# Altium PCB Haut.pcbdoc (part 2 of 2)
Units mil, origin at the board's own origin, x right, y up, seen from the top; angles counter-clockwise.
Board outline 4330.8 x 4330.8 mil, 2 copper layers (Top Layer, Bottom Layer), stack 62.2 mil thick; 77 components, 45 nets, 290 pads, 215 vias.
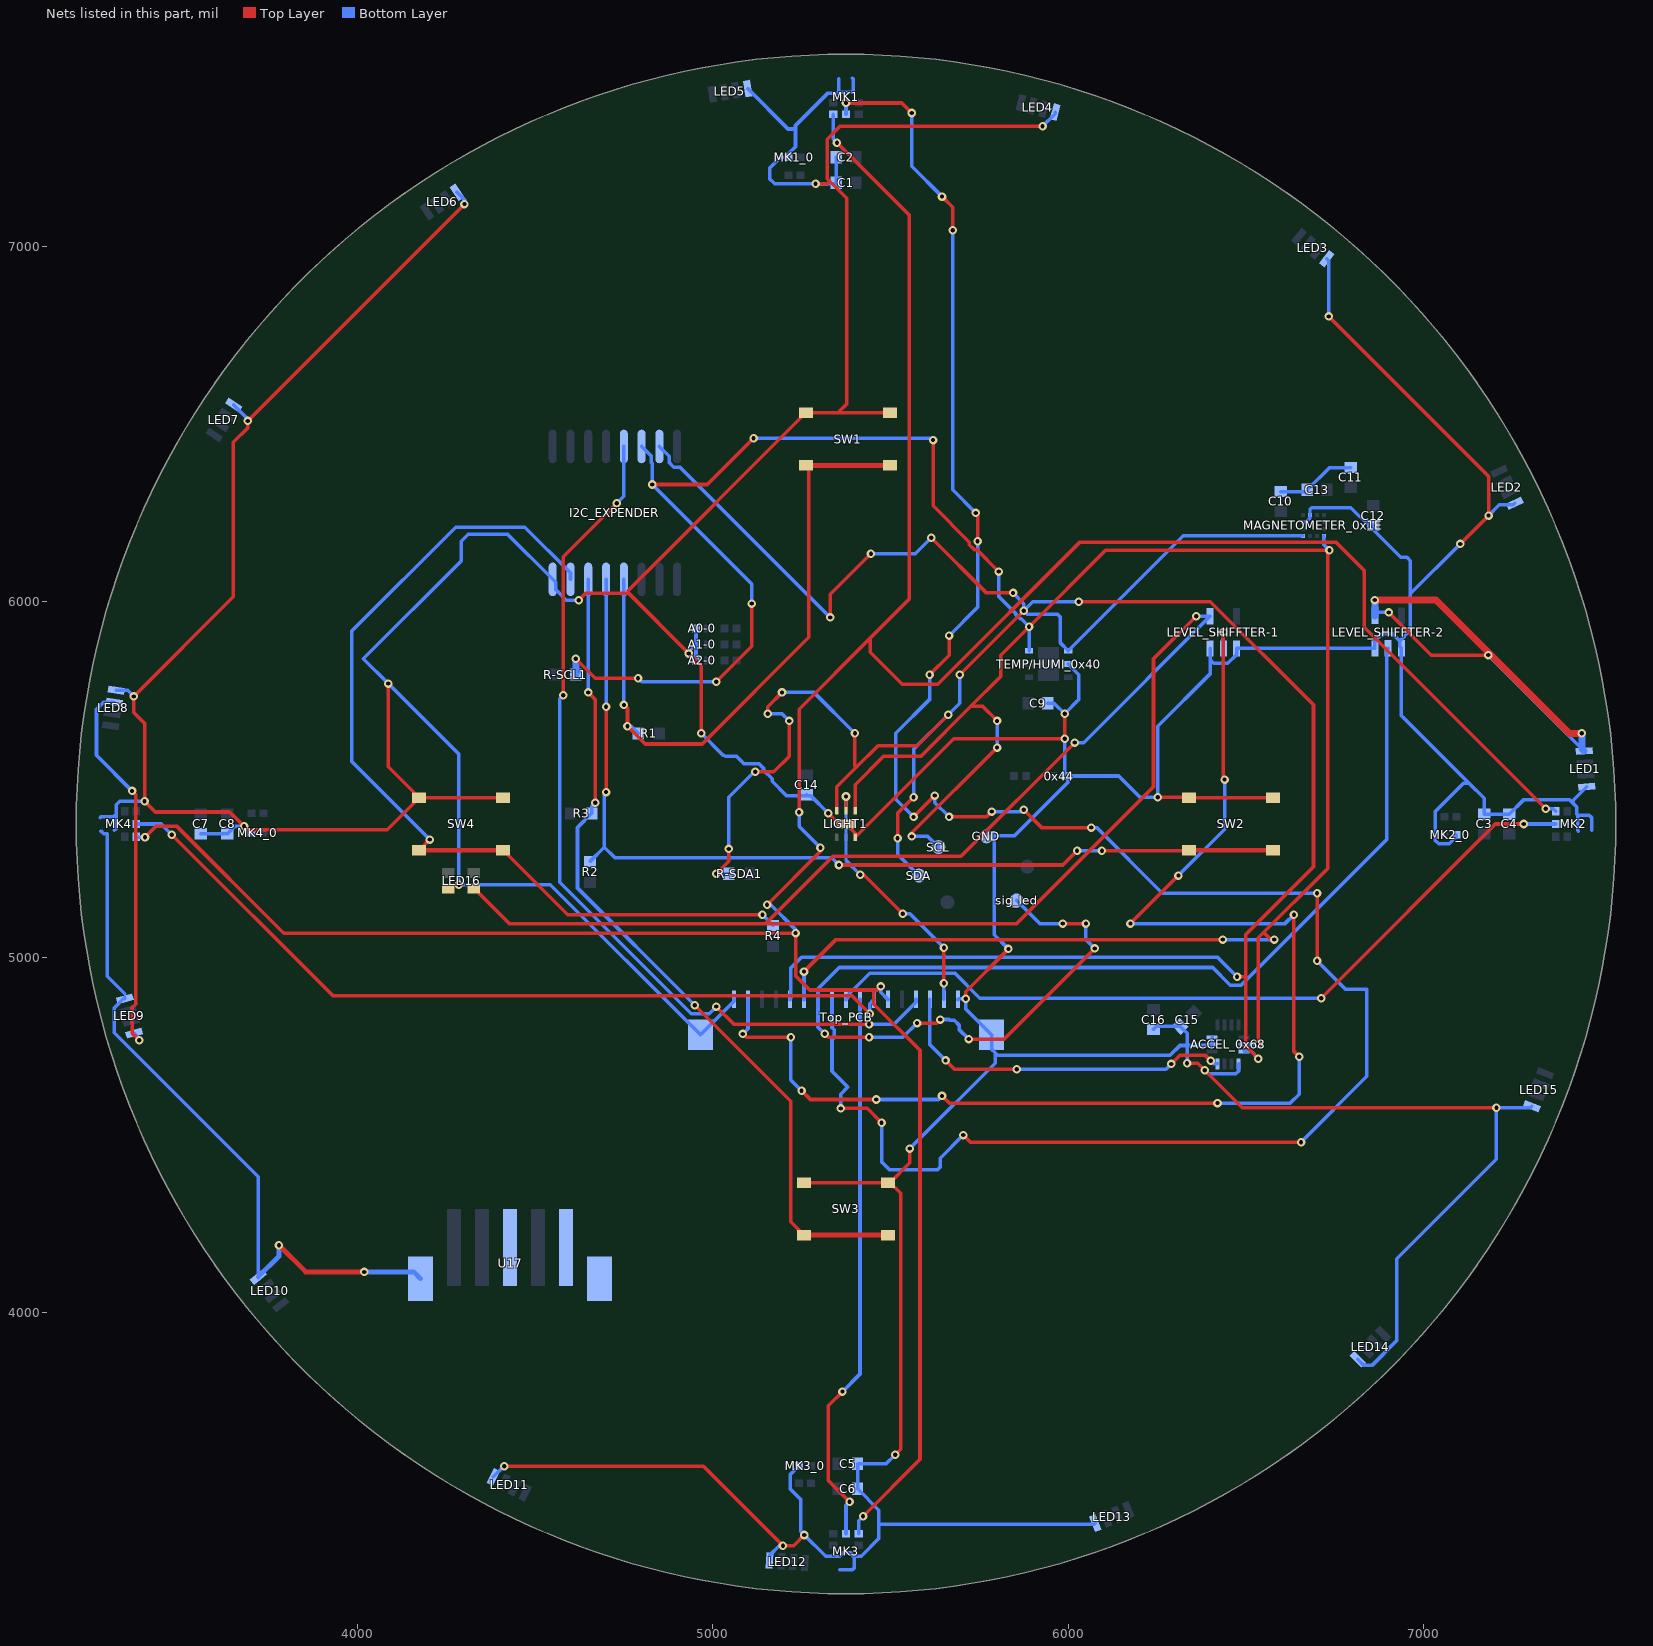
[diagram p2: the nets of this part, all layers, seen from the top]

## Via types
v1: diameter 24, hole 12, Top Layer to Bottom Layer, 215 vias

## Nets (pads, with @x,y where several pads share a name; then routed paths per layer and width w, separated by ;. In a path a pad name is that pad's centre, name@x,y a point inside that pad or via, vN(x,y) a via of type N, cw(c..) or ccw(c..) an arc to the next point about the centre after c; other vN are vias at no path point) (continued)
GND: 0x44.1 A0-0.1 A1-0.2 A2-0.2 ACCEL_0x68.1 ACCEL_0x68.6 ACCEL_0x68.7 C1.2 C2.2 C3.2 C4.2 C5.2 C6.2 C7.2 C8.2 C9.2 C10.1 C11.1 C12.1 C13.1 C14.1 C15.1 C16.1 GND.1 I2C_EXPENDER.8 LED1.4 LED2.4 LED3.4 LED4.4 LED5.4 LED6.4 LED7.4 LED8.4 LED9.4 LED10.4 LED11.4 LED12.4 LED13.4 LED14.4 LED15.4 LED16.2 LEVEL_SHIFFTER-1.1 LEVEL_SHIFFTER-1.3 LEVEL_SHIFFTER-2.1 LEVEL_SHIFFTER-2.3 LIGHT1.3 LIGHT1.7 MAGNETOMETER_0x1E.6 MAGNETOMETER_0x1E.8 MK1.3 MK1_0.2 MK2.3 MK2_0.2 MK3.3 MK3_0.2 MK4.3 MK4_0.2 SW1.1 SW1.2 SW2.1 SW2.2 SW3.1 SW3.2 SW4.1 SW4.2 TEMP/HUMI_0x40.2 Top_PCB.1 Top_PCB.17 Top_PCB.18 Top_PCB.19 U17.3 U17.5 U17.6 U17.7 | length 27844
  Top Layer w9.8: LIGHT1.7@5374.4,5374.4 5400,5348.8 LIGHT1.3@5400,5337 5677.4,5614.4 v1(5989.5,5614.4)
  Top Layer w10: v1(4086.8,5769.4) 4086.8,5535 SW4.1@4173.6,5448.2 ; LED16.2@4255.7,5193.4 4265.7,5203.4 v1(4285.7,5203.4) ; v1(4301.2,7118.2) v1(3691.2,6508.2) 3691.2,6488.2 3651.2,6448.2 3651.2,6013.2 v1(3371.2,5733.2) 3371.2,5688.2 3401.2,5658.2 v1(3401.2,5438.2) 3431.2,5408.2 3641.2,5408.2 v1(3681.2,5368.2) 3691.2,5358.2 4083.6,5358.2 SW4.1@4173.6,5448.2 ; SW4.2@4409.8,5448.2 SW4.1@4173.6,5448.2 ; v1(4413.4,3568) 4973.4,3568 v1(5197,3344.4) 5227,3344.4 v1(5257,3374.4) ; v1(4622.4,6004) 4642.4,6024 4762.4,6024 ; v1(4967,5629.4) 4967,5819.4 v1(4932.4,5854) 4762.4,6024 ; SW3.1@5256.3,4365.5 SW3.2@5492.5,4365.5 SW3.2@5498,4365.5 ; v1(5288.7,7175.3) 5322,7175.3 5328.8,7182.2 ; v1(5324.4,5404.4) 5354.4,5374.4 LIGHT1.7@5374.4,5374.4 ; SW1.2@5497.5,6530.9 5351.3,6530.9 ; v1(5513,3600.5) 5528,3615.5 5528,4335.5 SW3.2@5498,4365.5 ; v1(5553.9,4461.4) 5553.9,4421.4 SW3.2@5498,4365.5 ; v1(5711.4,4882.9) 5711.4,4902.9 v1(5831.4,5022.9) ; v1(5927.3,7336.9) 5357.3,7336.9 5321.3,7300.9 5321.3,7189.7 5328.8,7182.2 ; v1(5989.5,5614.4) v1(5989.5,5684.4) ; v1(6251.4,5449.4) 6337.8,5449.4 SW2.1@6339,5448.2 SW2.2@6575.2,5448.2 ; v1(6333.9,4701.4) 6363.9,4701.4 v1(6383.9,4681.4) 6488.9,4576.4 v1(7203.9,4576.4) ; v1(6732,6802.1) 7182,6352.1 v1(7182,6242.1) v1(7102,6162.1) ; 4762.4,6024 4762.4,6032 SW1.1@5261.3,6530.9 5351.3,6530.9 ; 5328.8,7182.2 5376.3,7134.7 5376.3,6555.9 5351.3,6530.9
  Top Layer w13.8: v1(3779.4,4189.4) 3854.4,4114.4 v1(4019.4,4114.4)
  Bottom Layer w9.8: C9.2@5942,5714.4 5959.5,5714.4 v1(5989.5,5684.4) ; C10.1@6597,6309.5 6667,6309.5 C13.1@6671.8,6314.4 6734.4,6377 C11.1@6794.4,6377 ; MAGNETOMETER_0x1E.6@6659.9,6224.2 6669.4,6224.2 6679.6,6234.4 MAGNETOMETER_0x1E.8@6679.6,6243.9 6679.6,6259.6 6684.4,6264.4 6794.4,6264.4 C12.1@6844.5,6214.3 ; C12.1@6857,6214.3 C12.1@6844.5,6214.3 ; 6962,6022.1 6962,6114.8 6952.4,6124.4 6934.4,6124.4 C12.1@6844.5,6214.3
  Bottom Layer w10: 3276.5,5392.2 3278.6,5394.3 3314.2,5394.3 3318.1,5398.2 3321.2,5398.2 ; 3278.6,5354.5 3286.5,5346.6 3296.3,5346.6 3296.3,4946.6 3345.9,4897 ; 3316.3,5356.6 3321.2,5361.5 3321.2,5398.2 ; LED8.4@3321.3,5750.4 3354,5750.4 v1(3371.2,5733.2) ; LED9.4@3345.9,4882.8 3345.9,4887 3315.9,4857 3315.9,4787 3721.2,4381.7 LED10.4@3721.2,4100.3 ; v1(3401.2,5438.2) 3331.2,5438.2 3321.2,5428.2 3321.2,5398.2 ; C7.2@3559.4,5346.8 C8.2@3634.4,5346.8 3655.8,5368.2 v1(3681.2,5368.2) 3683.5,5368.2 MK4_0.2@3702.4,5349.4 ; LED7.4@3651.8,6553 3691.2,6513.5 v1(3691.2,6508.2) ; LED6.4@4280.1,7151.7 4301.2,7130.6 v1(4301.2,7118.2) ; LED11.4@4382.4,3538 4412.4,3568 v1(4413.4,3568) ; v1(4622.4,6004) 4587.8,6004 4557.8,6034 4557.8,6054 I2C_EXPENDER.8@4549.4,6062.4 4422.4,6189.4 4311.8,6189.4 4291.8,6169.4 4291.8,6149.4 4291.8,6114.4 4016.8,5839.4 v1(4086.8,5769.4) 4285.7,5570.5 v1(4285.7,5203.4) 4542.9,5203.4 Top_PCB.19@4965,4781.4 5059.4,4875.9 Top_PCB.1@5059.4,4880.8 ; A0-0.1@4952.4,5924.4 A1-0.2@4952.4,5879.4 ; v1(4967,5629.4) 5027,5569.4 5036.8,5564.4 5066.8,5564.4 5086.8,5544.4 5128.9,5544.4 5142.4,5530.9 5142.4,5526.4 5166.8,5502 5166.8,5494.4 5206.8,5454.4 C14.1@5262,5454.4 ; LED5.4@5097.6,7443.2 5211.3,7329.4 5232.4,7329.4 ; LED12.4@5159.3,3302.9 5159.3,3316.8 5187,3344.4 v1(5197,3344.4) ; MK3_0.2@5242.4,3569.4 5217,3544 5217,3504.4 5247,3474.4 5247,3384.4 v1(5257,3374.4) 5317,3314.4 MK3.3@5357,3314.4 ; C14.1@5264.4,5456.8 C14.1@5262,5454.4 ; v1(5324.4,5404.4) 5274.4,5454.4 C14.1@5262,5454.4 ; C2.2@5346.8,7249.4 C1.2@5346.8,7178.1 5346.8,7175.3 v1(5288.7,7175.3) 5173.5,7175.3 5159.4,7189.4 5159.4,7219.4 5189.4,7249.4 MK1_0.2@5212.4,7249.4 5212.4,7259.4 5232.4,7279.4 5232.4,7329.4 ; 5354.5,3314.2 MK3.3@5357,3314.4 ; 5354.5,7470.2 5354.5,7434.6 5356.6,7432.5 ; 5356.6,3276.5 5392.2,3276.5 5394.3,3278.6 5397,3281.3 5397,3314.4 ; 5392.2,3316.3 5397,3314.4 ; 5392.2,7472.3 5394.3,7470.2 5394.3,7434.6 5392.2,7432.5 5356.6,7432.5 ; v1(5513,3600.5) 5486.9,3574.4 C5.2@5407,3574.4 C6.2@5407,3504.4 5467,3444.4 5467,3404.4 ; v1(5553.9,4461.4) 5793.9,4701.4 5793.9,4731.4 ; Top_PCB.17@5689.4,4880.8 5691.4,4882.9 v1(5711.4,4882.9) 5711.4,4853.8 Top_PCB.18@5783.9,4781.4 5783.9,4741.4 5793.9,4731.4 ; GND.1@5769.4,5349.4 5791.4,5349.4 ; v1(5831.4,5022.9) 5791.4,5062.9 5791.4,5349.4 ; v1(5927.3,7336.9) 5962.9,7372.5 LED4.4@5962.9,7376.9 ; v1(5989.5,5614.4) 5989.5,5511.3 0x44.1@5991.4,5509.4 ; v1(5989.5,5684.4) 6029.5,5724.4 6029.5,5794.4 TEMP/HUMI_0x40.2@5999.5,5824.4 ; LED13.4@6075.6,3407.6 6072.5,3404.4 5467,3404.4 ; C16.1@6239.4,4796.8 6247.5,4804.9 C15.1@6314.9,4804.9 6333.9,4786 6333.9,4751.4 ; v1(6333.9,4701.4) 6333.9,4751.4 ; v1(6383.9,4681.4) 6393.9,4671.4 6470.7,4671.4 6478.9,4679.6 ACCEL_0x68.1@6478.9,4699.6 ; LEVEL_SHIFFTER-1.3@6398.5,5868.2 6398.5,5836.4 ; ACCEL_0x68.7@6404.4,4774.1 ACCEL_0x68.6@6404.4,4754.4 6401.4,4751.4 6333.9,4751.4 ; LED3.4@6726.6,6964.4 6732,6959 v1(6732,6802.1) ; LED14.4@6813.9,3868.9 6831.4,3851.4 6853.9,3851.4 6923.9,3921.4 6923.9,4151.4 7203.9,4431.4 v1(7203.9,4576.4) 7299.9,4576.4 LED15.4@7303.6,4580.1 ; MK2_0.2@7091.4,5344.4 7091.4,5339 7071.4,5319 7041.4,5319 7031.4,5329 7031.4,5409 7111.4,5489 7126.8,5489 ; v1(7102,6162.1) 6962,6022.1 6962,5919 LEVEL_SHIFFTER-2.1@6932,5889 ; v1(7182,6242.1) 7212,6272.1 7251.1,6272.1 LED2.4@7255.6,6276.6 ; 7434.6,5354.5 7432.5,5356.6 7432.5,5392.2 7432.5,5399.4 ; LED1.4@7457.9,5479.3 7420,5441.4 7420,5432 ; 7472.3,5356.6 7472.3,5392.2 7470.2,5394.3 7465.1,5399.4 7432.5,5399.4 ; A1-0.2@4952.4,5879.4 A2-0.2@4952.4,5834.4 4932.8,5854 v1(4932.4,5854) 4932.4,5859.4 A1-0.2@4952.4,5879.4 ; 5232.4,7329.4 5232.4,7339.4 5322.4,7429.4 5353.5,7429.4 5356.6,7432.5 ; MK3.3@5357,3314.4 5367,3324.4 5387,3324.4 5397,3314.4 ; 5397,3314.4 5417,3314.4 5467,3364.4 5467,3404.4 ; 5791.4,5349.4 5798.9,5341.9 5848.9,5341.9 5998.9,5491.9 5998.9,5501.9 0x44.1@5991.4,5509.4 ; 5793.9,4731.4 5800.8,4724.4 6286.9,4724.4 6313.9,4751.4 6333.9,4751.4 ; 0x44.1@5991.4,5509.4 6141.4,5509.4 6201.4,5449.4 v1(6251.4,5449.4) 6251.4,5649.4 6398.5,5796.4 6398.5,5836.4 ; 6398.5,5836.4 6408.5,5826.4 6448.5,5826.4 6473.3,5851.2 LEVEL_SHIFFTER-1.1@6473.3,5868.2 6861.3,5868.2 LEVEL_SHIFFTER-2.3@6862,5869 6862,5889 6882,5909 6912,5909 LEVEL_SHIFFTER-2.1@6932,5889 ; LEVEL_SHIFFTER-2.1@6932,5889 6932,5873.8 LEVEL_SHIFFTER-2.1@6936.8,5869 6936.8,5679 7126.8,5489 ; 7126.8,5489 7169.4,5446.4 C3.2@7169.4,5402 C4.2@7240,5402 7280,5442 7410,5442 7420,5432 ; 7420,5432 7430,5422 7430,5402 7432.5,5399.4
  Bottom Layer w13.8: LED10.4@3721.2,4100.3 3779.4,4158.5 v1(3779.4,4189.4) ; v1(4019.4,4114.4) 4158.1,4114.4 U17.6@4177.4,4095.1
INT_ACCEL: ACCEL_0x68.4 Top_PCB.15 | length 993.8
  Top Layer w10: v1(5654.4,4709.4) 5679.4,4684.4 v1(5854.4,4684.4) ; v1(6289.4,4699.4) 6314.4,4724.4 6384.4,4724.4 v1(6400.5,4708.3)
  Bottom Layer w10: Top_PCB.15@5610.6,4880.8 5610.6,4753.2 v1(5654.4,4709.4) ; v1(5854.4,4684.4) 6274.4,4684.4 v1(6289.4,4699.4) ; v1@6399.4,4709.4 6409.2,4699.6 ACCEL_0x68.4@6419.9,4699.6
INT_EXT: I2C_EXPENDER.13 Top_PCB.14 | length 2518.1
  Top Layer w10: v1(4579.4,5736.4) 4579.4,6126.4 v1(4729.4,6276.4) ; v1(5009.4,4860.8) 5059.4,4810.8 v1(5439.4,4810.8)
  Bottom Layer w10: v1(4579.4,5736.4) 4569.4,5726.4 4569.4,5210.8 4939.4,4840.8 4989.4,4840.8 v1(5009.4,4860.8) ; v1(4729.4,6276.4) 4749.4,6296.4 I2C_EXPENDER.13@4749.4,6436.4 ; v1(5439.4,4810.8) 5509.4,4810.8 5571.3,4872.7 Top_PCB.14@5571.3,4880.8
INT_LUM: LIGHT1.5 Top_PCB.16 | length 742.7
  Top Layer w9.8: LIGHT1.5@5374.4,5411.8 v1(5374.4,5451.8) ; v1(5414.4,5231.8) 5424.4,5231.8 v1(5534.4,5121.8) ; v1(5650,4926.2) v1(5650,5026.2)
  Bottom Layer w9.8: v1(5374.4,5451.8) 5374.4,5271.8 v1(5414.4,5231.8) ; v1(5534.4,5121.8) 5554.4,5121.8 v1(5650,5026.2) ; Top_PCB.16@5650,4880.8 v1(5650,4926.2)
LED2: LED16.3 LEVEL_SHIFFTER-1.4 | length 5011.3
  Top Layer w10: LED16.3@4327.8,5193.4 4426.8,5094.4 ; v1(6017.8,5603.4) 5697.8,5283.4 5337.8,5283.4 5148.7,5094.4 ; v1(6359.4,5959.1) 6239.4,5839.1 6239.4,5479.4 5854.4,5094.4 5148.7,5094.4 ; 4426.8,5094.4 5148.7,5094.4 ; 4426.8,5094.4 4427.8,5093.4 5147.8,5093.4 5148.7,5094.4
  Bottom Layer w10: v1(6017.8,5603.4) 6042.8,5603.4 LEVEL_SHIFFTER-1.4@6398.5,5959.1 v1(6359.4,5959.1)
LED2-IN: LEVEL_SHIFFTER-1.2 Top_PCB.2 | length 3796.9
  Top Layer w10: v1(5084,4784) 5093.6,4774.4 v1(5219.4,4774.4) ; v1(5249.4,4624.4) 5274.4,4599.4 v1(5459.4,4599.4) ; v1(5644.4,4609.4) 5664.4,4589.4 v1(6419.4,4589.4) ; v1(6174.4,5094.4) v1(6309.4,5229.4) ; v1(6435.9,5914.4) 6435.9,5502.9 v1(6439.4,5499.4) ; v1(6634.4,5119.4) 6634.4,4734.4 v1(6649.4,4719.4)
  Bottom Layer w10: v1(5084,4784) 5098.8,4798.8 Top_PCB.2@5098.8,4880.8 ; v1(5219.4,4774.4) 5219.4,4654.4 v1(5249.4,4624.4) ; v1(5459.4,4599.4) 5634.4,4599.4 v1(5644.4,4609.4) ; v1(6174.4,5094.4) 6609.4,5094.4 v1(6634.4,5119.4) ; v1(6309.4,5229.4) 6439.4,5359.4 v1(6439.4,5499.4) ; v1(6419.4,4589.4) 6624.4,4589.4 6649.4,4614.4 v1(6649.4,4719.4) ; LEVEL_SHIFFTER-1.2@6435.9,5868.2 v1(6435.9,5914.4)
LED-9: LED8.3 LED9.1 | length 1073.6
  Top Layer w10: v1(3366.1,5467.4) 3376.1,5457.4 3376.1,4867.4 3366.1,4857.4 3366.1,4785.9 v1(3386.1,4765.9)
  Bottom Layer w10: LED8.3@3316.1,5717.4 3286.1,5717.4 3266.1,5697.4 3266.1,5567.4 v1(3366.1,5467.4) ; LED9.1@3371.9,4785.9 3386.1,4771.6 v1(3386.1,4765.9)
LED-ANNEAU: LED1.1 LEVEL_SHIFFTER-2.4 | length 1580.2
  Top Layer w10: v1(6900.9,5969.5) 7020.9,5849.5 v1(7180.9,5849.5)
  Top Layer w19.7: v1(6862,6004.4) 7034.4,6004.4 7409.4,5629.4 v1(7444.4,5629.4)
  Bottom Layer w10: LEVEL_SHIFFTER-2.4@6862,5959.8 6871.7,5969.5 v1(6900.9,5969.5) ; v1(7180.9,5849.5) LED1.1@7444.4,5586
  Bottom Layer w19.7: LEVEL_SHIFFTER-2.4@6862,5959.8 v1(6862,6004.4) ; v1(7444.4,5629.4) 7444.4,5586 LED1.1@7450.9,5579.5
LED-ANNEAU-IN: LEVEL_SHIFFTER-2.2 sig_led.1 Top_PCB.7 | length 3712.1
  Top Layer w10: v1(5314.4,4784.4) 5324.4,4774.4 v1(5439.4,4774.4) ; v1(5574.4,4814.4) 5629.4,4814.4 v1(5639.4,4824.4) ; v1(5719.4,4769.4) 5819.4,4769.4 v1(6074.4,5024.4) ; v1(5984.4,5094.4) v1(6049.4,5094.4)
  Bottom Layer w10: v1(5314.4,4784.4) 5295.7,4803.1 Top_PCB.7@5295.7,4880.8 5295.7,4910.8 5355.7,4970.8 6405.7,4970.8 6455.7,4920.8 6485.7,4920.8 6895.7,5330.8 6895.7,5865.2 LEVEL_SHIFFTER-2.2@6899.4,5869 ; v1(5439.4,4774.4) 5534.4,4774.4 v1(5574.4,4814.4) ; v1(5639.4,4824.4) 5664.4,4824.4 5666.4,4822.4 5678.9,4822.4 5692.4,4808.9 5692.4,4796.4 v1(5719.4,4769.4) ; sig_led.1@5854.4,5159.4 5919.4,5094.4 v1(5984.4,5094.4) ; v1(6049.4,5094.4) 6049.4,5049.4 v1(6074.4,5024.4)
MIC1: MK1.6 Top_PCB.8 | length 6405.2
  Top Layer w10: v1(5359.4,4574.4) 5434.4,4574.4 v1(5474.4,4534.4) ; v1(5374.4,7402.6) 5531.2,7402.6 v1(5559.4,7374.4) ; v1(5564.4,5394.4) v1(5624.4,5454.4) ; v1(5609.4,5794.4) 5664.4,5849.4 v1(5664.4,5904.4) ; v1(5644.4,7139.4) 5674.4,7109.4 v1(5674.4,7044.4) ; v1(5664.4,5394.4) 5769.4,5394.4 v1(5784.4,5409.4) ; v1(5704.4,4499.4) 5724.4,4479.4 v1(6654.4,4479.4) ; v1(5739.4,6249.4) 5744.4,6244.4 v1(5744.4,6169.4) ; v1(5874.2,5414.6) 5924.4,5364.4 v1(6064.4,5364.4) ; v1(6699.4,4989.4) v1(6699.4,5179.4)
  Bottom Layer w10: Top_PCB.8@5335,4880.8 5335,4801.7 5341.3,4795.5 5341.3,4773.3 5335,4767.1 5335,4678.8 5379.4,4634.4 5359.4,4614.4 v1(5359.4,4574.4) ; MK1.6@5374.4,7371 v1(5374.4,7402.6) ; v1(5474.4,4534.4) 5474.4,4424.4 5496.5,4402.3 5632.3,4402.3 5639.4,4409.4 5639.4,4434.4 v1(5704.4,4499.4) ; v1(5559.4,7374.4) 5559.4,7224.4 v1(5644.4,7139.4) ; v1(5564.4,5394.4) 5514.4,5444.4 5514.4,5629.4 5609.4,5724.4 v1(5609.4,5794.4) ; v1(5624.4,5454.4) 5624.4,5434.4 v1(5664.4,5394.4) ; v1(5664.4,5904.4) 5744.4,5984.4 v1(5744.4,6169.4) ; v1(5674.4,7044.4) 5674.4,6314.4 v1(5739.4,6249.4) ; v1(5784.4,5409.4) 5869.4,5409.4 v1@5874.4,5414.4 ; v1(6064.4,5364.4) 6079.4,5364.4 6264.4,5179.4 v1(6699.4,5179.4) ; v1(6654.4,4479.4) 6839.4,4664.4 6839.4,4909.4 6779.4,4909.4 v1(6699.4,4989.4)
MIC2: MK2.6 Top_PCB.9 | length 2263.1
  Top Layer w10: v1(6711,4884.4) 7201,5374.4 v1(7281,5374.4)
  Bottom Layer w10: Top_PCB.9@5374.4,4880.8 5381,4887.4 5381,4894.4 5441,4954.4 5681,4954.4 5751,4884.4 v1(6711,4884.4) ; v1(7281,5374.4) MK2.6@7371,5374.4
MIC3: MK3.6 Top_PCB.10 | length 1569
  Top Layer w10: v1(5364.4,3777.8) 5324.4,3737.8 5324.4,3527.8 v1(5384.4,3467.8)
  Bottom Layer w10: v1(5364.4,3777.8) 5413.8,3827.2 Top_PCB.10@5413.8,4880.8 ; MK3.6@5374.4,3377.8 5374.4,3457.8 v1(5384.4,3467.8)
MIC4: MK4.6 Top_PCB.11 | length 2329.5
  Top Layer w10: v1(3477.8,5344.4) 3931.4,4890.8 5391.4,4890.8 v1(5441.4,4840.8)
  Bottom Layer w10: MK4.6@3377.8,5374.4 3447.8,5374.4 v1(3477.8,5344.4) ; v1(5441.4,4840.8) 5441.4,4869.1 Top_PCB.11@5453.1,4880.8
SCL: ACCEL_0x68.13 I2C_EXPENDER.14 LIGHT1.4 MAGNETOMETER_0x1E.1 R-SCL1.1 SCL.1 TEMP/HUMI_0x40.6 Top_PCB.6 | length 8203.9
  Top Layer w9.8: LIGHT1.4@5400,5411.8 5400,5485 5479.4,5564.4 5584.4,5564.4 5725.3,5705.3 5809.4,5789.4 5809.4,5849.4 v1(5889.4,5929.4) 6104.4,6144.4 v1(6734.4,6144.4)
  Top Layer w10: v1(4614.4,5839.4) 4669.4,5784.4 v1(4789.4,5784.4) ; v1(4829.4,6329.4) 4984.4,6329.4 v1(5114.4,6459.4) ; v1(5009.4,5774.4) 5109.4,5874.4 v1(5109.4,5994.4) ; v1(5256.3,4959.4) 5346.3,5049.4 v1(6434.4,5049.4) ; v1(5559.4,5339.4) 5559.4,5349.4 v1(5799.4,5589.4) ; v1(5619.4,6454.4) 5619.4,6269.4 5721.4,6167.4 5721.4,6159.9 5734.9,6146.4 5742.4,6146.4 v1(5804.4,6084.4) ; 5725.3,5705.3 5758.5,5705.3 v1(5799.4,5664.4) ; v1(6534.4,4754.4) 6534.4,5054.4 6729.4,5249.4 6729.4,6139.4 v1(6734.4,6144.4) ; 6554.4,5064.4 6569.4,5049.4 v1(6579.4,5049.4)
  Bottom Layer w9.8: TEMP/HUMI_0x40.6@5889.3,5861.8 5889.3,5929.3 v1(5889.4,5929.4) ; MAGNETOMETER_0x1E.1@6718.9,6184.9 6718.9,6159.9 v1(6734.4,6144.4)
  Bottom Layer w10: v1(4789.4,5784.4) 4799.4,5774.4 v1(5009.4,5774.4) ; I2C_EXPENDER.14@4799.4,6436.4 4827.1,6408.7 4827.1,6391.2 4829.4,6389 v1(4829.4,6329.4) 5109.4,6049.4 v1(5109.4,5994.4) ; v1(5114.4,6459.4) 5614.4,6459.4 v1(5619.4,6454.4) ; Top_PCB.6@5256.3,4880.8 v1(5256.3,4959.4) ; v1(5559.4,5339.4) 5604.4,5339.4 SCL.1@5634.4,5309.4 ; v1(5799.4,5589.4) v1(5799.4,5664.4) ; v1(5804.4,6084.4) 5804.4,6014.4 5851.4,5967.4 5851.4,5964.9 5864.9,5951.4 5867.4,5951.4 v1(5889.4,5929.4) ; v1(6434.4,5049.4) v1(6579.4,5049.4) ; ACCEL_0x68.13@6494.4,4754.4 v1(6534.4,4754.4)
  Bottom Layer w19.7: R-SCL1.1@4614.1,5794.4 4614.4,5794.7 v1(4614.4,5839.4)
SDA: ACCEL_0x68.14 I2C_EXPENDER.15 LIGHT1.6 MAGNETOMETER_0x1E.4 R-SDA1.1 SDA.1 TEMP/HUMI_0x40.1 Top_PCB.5 | length 8417.5
  Top Layer w9.8: v1(5009.4,5234.4) 5044.4,5269.4 v1(5044.4,5304.4) ; LIGHT1.6@5348.8,5411.8 5348.8,5478.8 5403.6,5533.6 5464.4,5594.4 5574.4,5594.4 v1(5661.9,5681.9) ; v1(5694.4,5794.4) v1(5874.4,5974.4)
  Top Layer w10: v1(5119.4,5521.4) 5171.4,5521.4 5214.4,5564.4 v1(5214.4,5664.4) ; v1(5154.4,5684.4) 5154.4,5704.4 v1(5194.4,5744.4) ; v1(5330.4,5955.4) 5330.4,6020.4 v1(5444.4,6134.4) ; v1(5399.4,5629.4) 5399.4,5537.7 5403.6,5533.6 ; v1(5519.4,5334.4) 5519.4,5404.4 v1(5564.4,5449.4) ; v1(5614.4,6179.4) 5769.4,6024.4 v1(5844.4,6024.4) ; v1(6029.4,5999.4) 6399.4,5999.4 6689.4,5709.4 6689.4,5254.4 6499.4,5064.4 6499.4,4943.6 ; v1(6474.4,4944.4) 6498.6,4944.4 6499.4,4943.6 ; v1(6534.4,4714.4) 6499.4,4749.4 6499.4,4943.6
  Bottom Layer w9.8: v1(5009.4,5234.4) R-SDA1.1@5044.7,5234.4 ; v1(5044.4,5304.4) 5044.4,5449.4 ; v1(5661.9,5681.9) 5694.4,5714.4 v1(5694.4,5794.4) ; v1(5874.4,5974.4) 5884.4,5964.4 5969.4,5964.4 5976.4,5957.4 5976.4,5885 TEMP/HUMI_0x40.1@5999.5,5861.8 6322.6,6184.9 MAGNETOMETER_0x1E.4@6659.9,6184.9
  Bottom Layer w10: I2C_EXPENDER.15@4849.4,6436.4 4877.1,6408.7 4877.1,6391.2 4890.2,6378.2 4907.6,6378.2 v1(5330.4,5955.4) ; 5044.4,5449.4 v1@5119.4,5524.4 ; v1(5154.4,5684.4) 5194.4,5684.4 v1(5214.4,5664.4) ; v1(5194.4,5744.4) 5284.4,5744.4 v1(5399.4,5629.4) ; Top_PCB.5@5216.9,4880.8 5219.4,4883.3 5219.4,4969.4 5249.4,4999.4 6419.4,4999.4 v1(6474.4,4944.4) ; v1(5444.4,6134.4) 5569.4,6134.4 v1(5614.4,6179.4) ; v1(5519.4,5334.4) 5519.4,5289.4 SDA.1@5579.4,5229.4 ; v1(5564.4,5449.4) 5564.4,5584.4 v1(5661.9,5681.9) ; v1(5844.4,6024.4) 5874.4,5994.4 v1(5874.4,5974.4) 5899.4,5999.4 v1(6029.4,5999.4) ; ACCEL_0x68.14@6494.4,4734.7 6514.1,4734.7 v1(6534.4,4714.4)
SW1: I2C_EXPENDER.4 R1.2 SW1.3 SW1.4 | length 1834.1
  Top Layer w10: v1(4749.7,5709.4) 4759.7,5699.4 v1(4759.7,5649.4) 4809.7,5599.4 4969.7,5599.4 5269.7,5899.4 5269.7,6374.8 SW1.3@5261.3,6383.3
  Top Layer w13.8: SW1.3@5261.3,6383.3 SW1.4@5497.5,6383.3
  Bottom Layer w10: I2C_EXPENDER.4@4749.4,6062.4 4749.7,6062 v1(4749.7,5709.4) ; v1(4759.7,5649.4) 4769.7,5649.4 R1.2@4789.7,5629.4
SW2: I2C_EXPENDER.5 R2.2 SW2.3 SW2.4 | length 2730.6
  Top Layer w10: v1(4699.4,5464.1) v1(4699.4,5704.1) ; v1(5354.4,5259.1) 5984.4,5259.1 v1(6024.4,5299.1) ; v1(6094.4,5299.1) 6337.5,5299.1 SW2.3@6339,5300.6
  Top Layer w13.8: SW2.3@6339,5300.6 SW2.4@6575.2,5300.6
  Bottom Layer w10: R2.2@4654.4,5269.1 4694.4,5309.1 ; v1(4699.4,5464.1) 4694.4,5459.1 4694.4,5309.1 ; v1(4699.4,5704.1) I2C_EXPENDER.5@4699.4,6062.4 ; v1(5354.4,5259.1) 5334.4,5279.1 4724.4,5279.1 4694.4,5309.1 ; v1(6024.4,5299.1) v1(6094.4,5299.1)
SW3: I2C_EXPENDER.6 R3.2 SW3.3 SW3.4 | length 2373.7
  Top Layer w10: v1(4649.1,5744.4) 4669.1,5724.4 v1(4669.1,5434.4) ; v1(4949.1,4864.4) 5219.1,4594.4 5219.1,4255.1 SW3.3@5256.3,4217.9
  Top Layer w13.8: SW3.3@5256.3,4217.9 SW3.4@5492.5,4217.9
  Bottom Layer w10: v1(4649.1,5744.4) 4649.1,6062 I2C_EXPENDER.6@4649.4,6062.4 ; v1(4669.1,5434.4) 4659.1,5424.4 R3.2@4659.1,5404.4 4619.1,5364.4 4619.1,5194.4 v1(4949.1,4864.4)
SW4: I2C_EXPENDER.7 R4.2 SW4.3 SW4.4 | length 2611.7
  Top Layer w10: SW4.3@4173.6,5300.6 v1(4203.6,5330.6) ; SW4.4@4409.8,5300.6 4591.4,5119.1 v1(5139.4,5119.1)
  Top Layer w13.8: SW4.3@4173.6,5300.6 SW4.4@4409.8,5300.6
  Bottom Layer w10: v1(4203.6,5330.6) 3983.6,5550.6 3983.6,5916.6 4276.4,6209.4 4470.8,6209.4 4599.4,6080.8 I2C_EXPENDER.7@4599.4,6062.4 ; v1(5139.4,5119.1) R4.2@5169.4,5089.1
WS: MK1.1 MK2.1 MK3.1 MK4.1 Top_PCB.12 | length 9298.2
  Top Layer w10: v1(3402.5,5337.5) 3432.5,5367.5 3492.5,5367.5 3792.5,5067.5 v1(5232.5,5067.5) 5232.5,4947.5 5272.5,4907.5 5452.5,4907.5 ; v1(5152.5,5147.5) 5302.5,5297.5 v1(5302.5,5307.5) ; v1(5242.5,5407.5) 5242.5,5697.5 5442.5,5897.5 ; v1(5349,7291) 5552.5,7087.5 5552.5,6007.5 5442.5,5897.5 ; v1(5422.5,3427.5) 5582.5,3587.5 5582.5,4737.5 5452.5,4867.5 5452.5,4907.5 ; v1(5472.5,4917.5) 5462.5,4907.5 5452.5,4907.5 ; v1(7342.5,5417.5) 6832.5,5927.5 6832.5,6087.5 6752.5,6167.5 6032.5,6167.5 5632.5,5767.5 5532.5,5767.5 5442.5,5857.5 5442.5,5897.5
  Bottom Layer w10: MK4.1@3377.8,5339 3379.3,5337.5 v1(3402.5,5337.5) ; v1(5152.5,5147.5) 5162.5,5147.5 5232.5,5077.5 v1(5232.5,5067.5) ; v1(5242.5,5407.5) 5242.5,5367.5 v1(5302.5,5307.5) ; MK1.1@5339,7371 5339,7301 v1(5349,7291) ; MK3.1@5409.8,3377.8 5409.8,3414.8 v1(5422.5,3427.5) ; v1(5472.5,4917.5) 5472.5,4900.8 Top_PCB.12@5492.5,4880.8 ; v1(7342.5,5417.5) 7363.4,5417.5 MK2.1@7371,5409.8
pads on no net: ACCEL_0x68.2 ACCEL_0x68.3 ACCEL_0x68.9 ACCEL_0x68.10 ACCEL_0x68.11 ACCEL_0x68.12 I2C_EXPENDER.9 I2C_EXPENDER.10 I2C_EXPENDER.11 I2C_EXPENDER.12 LED15.3 LED16.1 MAGNETOMETER_0x1E.2 MAGNETOMETER_0x1E.7 MAGNETOMETER_0x1E.11 MAGNETOMETER_0x1E.12 TEMP/HUMI_0x40.3 TEMP/HUMI_0x40.4 TEMP/HUMI_0x40.7

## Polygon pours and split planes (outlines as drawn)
GND on Bottom Layer (solid, remove dead copper, pour order 2): 335 vertices, not listed, extent 3119.4,3109.8 7636.8,7626.9
GND on Top Layer (solid, remove dead copper, pour order 0): 344 vertices, not listed, extent 3000.1,3000 7748.8,7748.8

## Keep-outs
Board Outline Layer:
  region: 4433.1,4629.4 4432.8,4621.6 4431.6,4613.8 4429.6,4606.2 4427,4598.8 4423.6,4591.7 4419.5,4585 4414.7,4578.8 4409.4,4573 4403.5,4567.8 4397.1,4563.3 4390.3,4559.3 4383.2,4556.1 4375.7,4553.6 4368.1,4551.9 4360.3,4550.9 4352.4,4550.7 4344.6,4551.3 4336.9,4552.6 4329.3,4554.8 4322,4557.6 4315,4561.2 4308.4,4565.5 4302.3,4570.4 4296.7,4575.8 4291.6,4581.9 4287.2,4588.3 4283.5,4595.2 4280.4,4602.5 4278.1,4610 4276.5,4617.7 4275.8,4625.5 4275.8,4633.3 4276.5,4641.1 4278.1,4648.8 4280.4,4656.3 4283.5,4663.6 4287.2,4670.5 4291.6,4676.9 4296.7,4683 4302.3,4688.4 4308.4,4693.3 4315,4697.6 4322,4701.2 4329.3,4704 4336.9,4706.2 4344.6,4707.5 4352.4,4708.1 4360.3,4707.9 4368.1,4706.9 4375.7,4705.2 4383.2,4702.7 4390.3,4699.5 4397.1,4695.5 4403.5,4691 4409.4,4685.8 4414.7,4680 4419.5,4673.8 4423.6,4667.1 4427,4660 4429.6,4652.6 4431.6,4645 4432.8,4637.2
  region: 4433.1,4629.4 4432.8,4621.6 4431.6,4613.8 4429.6,4606.2 4427,4598.8 4423.6,4591.7 4419.5,4585 4414.7,4578.8 4409.4,4573 4403.5,4567.8 4397.1,4563.3 4390.3,4559.3 4383.2,4556.1 4375.7,4553.6 4368.1,4551.9 4360.3,4550.9 4352.4,4550.7 4344.6,4551.3 4336.9,4552.6 4329.3,4554.8 4322,4557.6 4315,4561.2 4308.4,4565.5 4302.3,4570.4 4296.7,4575.8 4291.6,4581.9 4287.2,4588.3 4283.5,4595.2 4280.4,4602.5 4278.1,4610 4276.5,4617.7 4275.8,4625.5 4275.8,4633.3 4276.5,4641.1 4278.1,4648.8 4280.4,4656.3 4283.5,4663.6 4287.2,4670.5 4291.6,4676.9 4296.7,4683 4302.3,4688.4 4308.4,4693.3 4315,4697.6 4322,4701.2 4329.3,4704 4336.9,4706.2 4344.6,4707.5 4352.4,4708.1 4360.3,4707.9 4368.1,4706.9 4375.7,4705.2 4383.2,4702.7 4390.3,4699.5 4397.1,4695.5 4403.5,4691 4409.4,4685.8 4414.7,4680 4419.5,4673.8 4423.6,4667.1 4427,4660 4429.6,4652.6 4431.6,4645 4432.8,4637.2
  region: 4468.1,6319.3 4467.8,6311.4 4466.6,6303.7 4464.6,6296.1 4462,6288.7 4458.6,6281.6 4454.5,6274.9 4449.7,6268.7 4444.4,6262.9 4438.5,6257.7 4432.1,6253.1 4425.3,6249.2 4418.2,6246 4410.7,6243.5 4403.1,6241.7 4395.3,6240.8 4387.4,6240.6 4379.6,6241.2 4371.9,6242.5 4364.3,6244.6 4357,6247.5 4350,6251.1 4343.4,6255.4 4337.3,6260.2 4331.7,6265.7 4326.6,6271.7 4322.2,6278.2 4318.5,6285.1 4315.4,6292.4 4313.1,6299.9 4311.5,6307.5 4310.8,6315.4 4310.8,6323.2 4311.5,6331 4313.1,6338.7 4315.4,6346.2 4318.5,6353.4 4322.2,6360.3 4326.6,6366.8 4331.7,6372.8 4337.3,6378.3 4343.4,6383.2 4350,6387.5 4357,6391.1 4364.3,6393.9 4371.9,6396.1 4379.6,6397.4 4387.4,6398 4395.3,6397.8 4403.1,6396.8 4410.7,6395.1 4418.2,6392.6 4425.3,6389.4 4432.1,6385.4 4438.5,6380.8 4444.4,6375.7 4449.7,6369.9 4454.5,6363.6 4458.6,6356.9 4462,6349.9 4464.6,6342.5 4466.6,6334.9 4467.8,6327.1
  region: 4468.1,6319.3 4467.8,6311.4 4466.6,6303.7 4464.6,6296.1 4462,6288.7 4458.6,6281.6 4454.5,6274.9 4449.7,6268.7 4444.4,6262.9 4438.5,6257.7 4432.1,6253.1 4425.3,6249.2 4418.2,6246 4410.7,6243.5 4403.1,6241.7 4395.3,6240.8 4387.4,6240.6 4379.6,6241.2 4371.9,6242.5 4364.3,6244.6 4357,6247.5 4350,6251.1 4343.4,6255.4 4337.3,6260.2 4331.7,6265.7 4326.6,6271.7 4322.2,6278.2 4318.5,6285.1 4315.4,6292.4 4313.1,6299.9 4311.5,6307.5 4310.8,6315.4 4310.8,6323.2 4311.5,6331 4313.1,6338.7 4315.4,6346.2 4318.5,6353.4 4322.2,6360.3 4326.6,6366.8 4331.7,6372.8 4337.3,6378.3 4343.4,6383.2 4350,6387.5 4357,6391.1 4364.3,6393.9 4371.9,6396.1 4379.6,6397.4 4387.4,6398 4395.3,6397.8 4403.1,6396.8 4410.7,6395.1 4418.2,6392.6 4425.3,6389.4 4432.1,6385.4 4438.5,6380.8 4444.4,6375.7 4449.7,6369.9 4454.5,6363.6 4458.6,6356.9 4462,6349.9 4464.6,6342.5 4466.6,6334.9 4467.8,6327.1
  region: 6516.1,6319.3 6515.7,6311.4 6514.6,6303.7 6512.6,6296.1 6510,6288.7 6506.6,6281.6 6502.5,6274.9 6497.7,6268.7 6492.4,6262.9 6486.5,6257.7 6480.1,6253.1 6473.3,6249.2 6466.2,6246 6458.7,6243.5 6451.1,6241.7 6443.3,6240.8 6435.4,6240.6 6427.6,6241.2 6419.9,6242.5 6412.3,6244.6 6405,6247.5 6398,6251.1 6391.4,6255.4 6385.3,6260.2 6379.7,6265.7 6374.6,6271.7 6370.2,6278.2 6366.5,6285.1 6363.4,6292.4 6361.1,6299.9 6359.5,6307.5 6358.8,6315.4 6358.8,6323.2 6359.5,6331 6361.1,6338.7 6363.4,6346.2 6366.5,6353.4 6370.2,6360.3 6374.6,6366.8 6379.7,6372.8 6385.3,6378.3 6391.4,6383.2 6398,6387.5 6405,6391.1 6412.3,6393.9 6419.9,6396.1 6427.6,6397.4 6435.4,6398 6443.3,6397.8 6451.1,6396.8 6458.7,6395.1 6466.2,6392.6 6473.3,6389.4 6480.1,6385.4 6486.5,6380.8 6492.4,6375.7 6497.7,6369.9 6502.5,6363.6 6506.6,6356.9 6510,6349.9 6512.6,6342.5 6514.6,6334.9 6515.7,6327.1
  region: 6516.1,6319.3 6515.7,6311.4 6514.6,6303.7 6512.6,6296.1 6510,6288.7 6506.6,6281.6 6502.5,6274.9 6497.7,6268.7 6492.4,6262.9 6486.5,6257.7 6480.1,6253.1 6473.3,6249.2 6466.2,6246 6458.7,6243.5 6451.1,6241.7 6443.3,6240.8 6435.4,6240.6 6427.6,6241.2 6419.9,6242.5 6412.3,6244.6 6405,6247.5 6398,6251.1 6391.4,6255.4 6385.3,6260.2 6379.7,6265.7 6374.6,6271.7 6370.2,6278.2 6366.5,6285.1 6363.4,6292.4 6361.1,6299.9 6359.5,6307.5 6358.8,6315.4 6358.8,6323.2 6359.5,6331 6361.1,6338.7 6363.4,6346.2 6366.5,6353.4 6370.2,6360.3 6374.6,6366.8 6379.7,6372.8 6385.3,6378.3 6391.4,6383.2 6398,6387.5 6405,6391.1 6412.3,6393.9 6419.9,6396.1 6427.6,6397.4 6435.4,6398 6443.3,6397.8 6451.1,6396.8 6458.7,6395.1 6466.2,6392.6 6473.3,6389.4 6480.1,6385.4 6486.5,6380.8 6492.4,6375.7 6497.7,6369.9 6502.5,6363.6 6506.6,6356.9 6510,6349.9 6512.6,6342.5 6514.6,6334.9 6515.7,6327.1
  region: 6188.1,4344.4 6187.8,4336.6 6186.6,4328.8 6184.6,4321.2 6182,4313.8 6178.6,4306.7 6174.5,4300 6169.7,4293.8 6164.4,4288 6158.5,4282.8 6152.1,4278.3 6145.3,4274.3 6138.2,4271.1 6130.7,4268.6 6123.1,4266.9 6115.3,4265.9 6107.4,4265.7 6099.6,4266.3 6091.9,4267.6 6084.3,4269.8 6077,4272.6 6070,4276.2 6063.4,4280.5 6057.3,4285.4 6051.7,4290.8 6046.6,4296.9 6042.2,4303.3 6038.5,4310.2 6035.4,4317.5 6033.1,4325 6031.5,4332.7 6030.8,4340.5 6030.8,4348.3 6031.5,4356.1 6033.1,4363.8 6035.4,4371.3 6038.5,4378.6 6042.2,4385.5 6046.6,4391.9 6051.7,4398 6057.3,4403.4 6063.4,4408.3 6070,4412.6 6077,4416.2 6084.3,4419 6091.9,4421.2 6099.6,4422.5 6107.4,4423.1 6115.3,4422.9 6123.1,4421.9 6130.7,4420.2 6138.2,4417.7 6145.3,4414.5 6152.1,4410.5 6158.5,4406 6164.4,4400.8 6169.7,4395 6174.5,4388.8 6178.6,4382.1 6182,4375 6184.6,4367.6 6186.6,4360 6187.8,4352.2
  region: 6188.1,4344.4 6187.8,4336.6 6186.6,4328.8 6184.6,4321.2 6182,4313.8 6178.6,4306.7 6174.5,4300 6169.7,4293.8 6164.4,4288 6158.5,4282.8 6152.1,4278.3 6145.3,4274.3 6138.2,4271.1 6130.7,4268.6 6123.1,4266.9 6115.3,4265.9 6107.4,4265.7 6099.6,4266.3 6091.9,4267.6 6084.3,4269.8 6077,4272.6 6070,4276.2 6063.4,4280.5 6057.3,4285.4 6051.7,4290.8 6046.6,4296.9 6042.2,4303.3 6038.5,4310.2 6035.4,4317.5 6033.1,4325 6031.5,4332.7 6030.8,4340.5 6030.8,4348.3 6031.5,4356.1 6033.1,4363.8 6035.4,4371.3 6038.5,4378.6 6042.2,4385.5 6046.6,4391.9 6051.7,4398 6057.3,4403.4 6063.4,4408.3 6070,4412.6 6077,4416.2 6084.3,4419 6091.9,4421.2 6099.6,4422.5 6107.4,4423.1 6115.3,4422.9 6123.1,4421.9 6130.7,4420.2 6138.2,4417.7 6145.3,4414.5 6152.1,4410.5 6158.5,4406 6164.4,4400.8 6169.7,4395 6174.5,4388.8 6178.6,4382.1 6182,4375 6184.6,4367.6 6186.6,4360 6187.8,4352.2
  lines w0.1: 4275.8,4625.5 4276.5,4617.7 4278.1,4610 4280.4,4602.5 4283.5,4595.2 4287.2,4588.3 4291.6,4581.9 4296.7,4575.8 4302.3,4570.4 4308.4,4565.5 4315,4561.2 4322,4557.6 4329.3,4554.8 4336.9,4552.6 4344.6,4551.3 4352.4,4550.7 4360.3,4550.9 4368.1,4551.9 4375.7,4553.6 4383.2,4556.1 4390.3,4559.3 4397.1,4563.3 4403.5,4567.8 4409.4,4573 4414.7,4578.8 4419.5,4585 4423.6,4591.7 4427,4598.8 4429.6,4606.2 4431.6,4613.8 4432.8,4621.6 4433.1,4629.4 4432.8,4637.2 4431.6,4645 4429.6,4652.6 4427,4660 4423.6,4667.1 4419.5,4673.8 4414.7,4680 4409.4,4685.8 4403.5,4691 4397.1,4695.5 4390.3,4699.5 4383.2,4702.7 4375.7,4705.2 4368.1,4706.9 4360.3,4707.9 4352.4,4708.1 4344.6,4707.5 4336.9,4706.2 4329.3,4704 4322,4701.2 4315,4697.6 4308.4,4693.3 4302.3,4688.4 4296.7,4683 4291.6,4676.9 4287.2,4670.5 4283.5,4663.6 4280.4,4656.3 4278.1,4648.8 4276.5,4641.1 4275.8,4633.3 4275.8,4625.5 ; 4310.8,6315.4 4311.5,6307.5 4313.1,6299.9 4315.4,6292.4 4318.5,6285.1 4322.2,6278.2 4326.6,6271.7 4331.7,6265.7 4337.3,6260.2 4343.4,6255.4 4350,6251.1 4357,6247.5 4364.3,6244.6 4371.9,6242.5 4379.6,6241.2 4387.4,6240.6 4395.3,6240.8 4403.1,6241.7 4410.7,6243.5 4418.2,6246 4425.3,6249.2 4432.1,6253.1 4438.5,6257.7 4444.4,6262.9 4449.7,6268.7 4454.5,6274.9 4458.6,6281.6 4462,6288.7 4464.6,6296.1 4466.6,6303.7 4467.8,6311.4 4468.1,6319.3 4467.8,6327.1 4466.6,6334.9 4464.6,6342.5 4462,6349.9 4458.6,6356.9 4454.5,6363.6 4449.7,6369.9 4444.4,6375.7 4438.5,6380.8 4432.1,6385.4 4425.3,6389.4 4418.2,6392.6 4410.7,6395.1 4403.1,6396.8 4395.3,6397.8 4387.4,6398 4379.6,6397.4 4371.9,6396.1 4364.3,6393.9 4357,6391.1 4350,6387.5 4343.4,6383.2 4337.3,6378.3 4331.7,6372.8 4326.6,6366.8 4322.2,6360.3 4318.5,6353.4 4315.4,6346.2 4313.1,6338.7 4311.5,6331 4310.8,6323.2 4310.8,6315.4 ; 6030.8,4340.5 6031.5,4332.7 6033.1,4325 6035.4,4317.5 6038.5,4310.2 6042.2,4303.3 6046.6,4296.9 6051.7,4290.8 6057.3,4285.4 6063.4,4280.5 6070,4276.2 6077,4272.6 6084.3,4269.8 6091.9,4267.6 6099.6,4266.3 6107.4,4265.7 6115.3,4265.9 6123.1,4266.9 6130.7,4268.6 6138.2,4271.1 6145.3,4274.3 6152.1,4278.3 6158.5,4282.8 6164.4,4288 6169.7,4293.8 6174.5,4300 6178.6,4306.7 6182,4313.8 6184.6,4321.2 6186.6,4328.8 6187.8,4336.6 6188.1,4344.4 6187.8,4352.2 6186.6,4360 6184.6,4367.6 6182,4375 6178.6,4382.1 6174.5,4388.8 6169.7,4395 6164.4,4400.8 6158.5,4406 6152.1,4410.5 6145.3,4414.5 6138.2,4417.7 6130.7,4420.2 6123.1,4421.9 6115.3,4422.9 6107.4,4423.1 6099.6,4422.5 6091.9,4421.2 6084.3,4419 6077,4416.2 6070,4412.6 6063.4,4408.3 6057.3,4403.4 6051.7,4398 6046.6,4391.9 6042.2,4385.5 6038.5,4378.6 6035.4,4371.3 6033.1,4363.8 6031.5,4356.1 6030.8,4348.3 6030.8,4340.5 ; 6358.8,6315.4 6359.5,6307.5 6361.1,6299.9 6363.4,6292.4 6366.5,6285.1 6370.2,6278.2 6374.6,6271.7 6379.7,6265.7 6385.3,6260.2 6391.4,6255.4 6398,6251.1 6405,6247.5 6412.3,6244.6 6419.9,6242.5 6427.6,6241.2 6435.4,6240.6 6443.3,6240.8 6451.1,6241.7 6458.7,6243.5 6466.2,6246 6473.3,6249.2 6480.1,6253.1 6486.5,6257.7 6492.4,6262.9 6497.7,6268.7 6502.5,6274.9 6506.6,6281.6 6510,6288.7 6512.6,6296.1 6514.6,6303.7 6515.7,6311.4 6516.1,6319.3 6515.7,6327.1 6514.6,6334.9 6512.6,6342.5 6510,6349.9 6506.6,6356.9 6502.5,6363.6 6497.7,6369.9 6492.4,6375.7 6486.5,6380.8 6480.1,6385.4 6473.3,6389.4 6466.2,6392.6 6458.7,6395.1 6451.1,6396.8 6443.3,6397.8 6435.4,6398 6427.6,6397.4 6419.9,6396.1 6412.3,6393.9 6405,6391.1 6398,6387.5 6391.4,6383.2 6385.3,6378.3 6379.7,6372.8 6374.6,6366.8 6370.2,6360.3 6366.5,6353.4 6363.4,6346.2 6361.1,6338.7 6359.5,6331 6358.8,6323.2 6358.8,6315.4
  lines w10: 3209.2,5353.6 3210,5312 3211.6,5270.4 3213.9,5228.9 3217.1,5187.4 3221.1,5146 3225.9,5104.7 3231.5,5063.4 3237.9,5022.3 3245,4981.3 3253,4940.5 3261.7,4899.8 3271.2,4859.3 3281.5,4819 3292.6,4778.9 3304.4,4739 3317,4699.3 3330.3,4659.9 3344.4,4620.8 3359.3,4581.9 3374.9,4543.4 3391.2,4505.1 3408.3,4467.1 3426.1,4429.5 3444.6,4392.3 3463.8,4355.4 3483.7,4318.9 3504.4,4282.7 3525.7,4247 3547.7,4211.7 3570.4,4176.8 3593.7,4142.4 3617.7,4108.4 3642.4,4074.9 3667.7,4041.8 3693.6,4009.3 3720.1,3977.2 3747.3,3945.7 3775,3914.7 3803.4,3884.2 3832.3,3854.3 3861.8,3825 3891.8,3796.2 3922.4,3768 3953.5,3740.4 3985.2,3713.4 4017.4,3687 4050,3661.3 4083.2,3636.1 4116.8,3611.7 4150.9,3587.8 4185.5,3564.6 4220.5,3542.1 4255.9,3520.3 4291.7,3499.2 4328,3478.7 4364.6,3458.9 4401.6,3439.9 4438.9,3421.6 4476.6,3403.9 4514.6,3387.1 4553,3370.9 4591.6,3355.5 4630.6,3340.8 4669.8,3326.9 4709.2,3313.7 4748.9,3301.3 4788.9,3289.7 4829.1,3278.8 4869.4,3268.8 4910,3259.4 4950.7,3250.9 4991.6,3243.2 5032.6,3236.2 5073.7,3230 5115,3224.6 5156.3,3220.1 5197.8,3216.3 5239.3,3213.3 5280.8,3211.1 5322.4,3209.7 5364,3209.1 5405.6,3209.3 5447.2,3210.3 5488.8,3212.1 5530.3,3214.7 5571.8,3218.1 5613.2,3222.3 5654.5,3227.2 5695.7,3233 5736.8,3239.6 5777.7,3246.9 5818.5,3255.1 5859.1,3264 5899.6,3273.7 5939.9,3284.2 5979.9,3295.4 6019.8,3307.5 6059.3,3320.2 6098.7,3333.8 6137.8,3348.1 6176.6,3363.1 6215.1,3378.9 6253.2,3395.4 6291.1,3412.7 6328.6,3430.6 6365.8,3449.3 6402.6,3468.7 6439,3488.8 6475.1,3509.6 6510.7,3531.1 6545.9,3553.3 6580.7,3576.1 6615,3599.7 6648.9,3623.8 6682.3,3648.6 6715.2,3674.1 6747.6,3700.1 6779.5,3726.8 6810.9,3754.1 6841.8,3782 6872.1,3810.5 6901.9,3839.6 6931.1,3869.2 6959.7,3899.4 6987.7,3930.1 7015.2,3961.4 7042,3993.2 7068.3,4025.5 7093.9,4058.3 7118.9,4091.6 7143.2,4125.3 7166.8,4159.5 7189.9,4194.2 7212.2,4229.3 7233.9,4264.8 7254.8,4300.7 7275.1,4337.1 7294.7,4373.8 7313.6,4410.9 7331.7,4448.3 7349.2,4486.1 7365.9,4524.2 7381.8,4562.6 7397.1,4601.3 7411.5,4640.3 7425.3,4679.6 7438.2,4719.1 7450.4,4758.9 7461.9,4798.9 7472.6,4839.1 7482.5,4879.5 7491.6,4920.1 7499.9,4960.9 7507.5,5001.8 7514.2,5042.9 7520.2,5084 7525.4,5125.3 7529.8,5166.7 7533.4,5208.1 7536.2,5249.7 7538.2,5291.2 7539.4,5332.8 7539.8,5374.4 7539.4,5416 7538.2,5457.6 7536.2,5499.2 7533.4,5540.7 7529.8,5582.1 7525.4,5623.5 7520.2,5664.8 7514.2,5705.9 7507.5,5747 7499.9,5787.9 7491.6,5828.7 7482.5,5869.3 7472.6,5909.7 7461.9,5949.9 7450.4,5989.9 7438.2,6029.7 7425.3,6069.2 7411.5,6108.5 7397.1,6147.5 7381.8,6186.2 7365.9,6224.6 7349.2,6262.7 7331.7,6300.5 7313.6,6337.9 7294.7,6375 7275.1,6411.7 7254.8,6448.1 7233.9,6484 7212.2,6519.5 7189.9,6554.6 7166.8,6589.3 7143.2,6623.5 7118.9,6657.2 7093.9,6690.5 7068.3,6723.3 7042,6755.6 7015.2,6787.4 6987.7,6818.7 6959.7,6849.4 6931.1,6879.6 6901.9,6909.2 6872.1,6938.3 6841.8,6966.8 6810.9,6994.7 6779.5,7022 6747.6,7048.7 6715.2,7074.7 6682.3,7100.2 6648.9,7125 6615,7149.2 6580.7,7172.7 6545.9,7195.5 6510.7,7217.7 6475.1,7239.2 6439,7260 6402.6,7280.1 6365.8,7299.5 6328.6,7318.2 6291.1,7336.1 6253.2,7353.4 6215.1,7369.9 6176.6,7385.7 6137.8,7400.7 6098.7,7415 6059.3,7428.6 6019.8,7441.4 5979.9,7453.4 5939.9,7464.6 5899.6,7475.1 5859.1,7484.8 5818.5,7493.7 5777.7,7501.9 5736.8,7509.2 5695.7,7515.8 5654.5,7521.6 5613.2,7526.6 5571.8,7530.7 5530.3,7534.1 5488.8,7536.7 5447.2,7538.5 5405.6,7539.5 5364,7539.7 5322.4,7539.1 5280.8,7537.7 5239.3,7535.5 5197.8,7532.5 5156.3,7528.7 5115,7524.2 5073.7,7518.8 5032.6,7512.6 4991.6,7505.6 4950.7,7497.9 4910,7489.4 4869.4,7480 4829.1,7470 4788.9,7459.1 4748.9,7447.5 4709.2,7435.1 4669.8,7421.9 4630.6,7408 4591.6,7393.3 4553,7377.9 4514.6,7361.7 4476.6,7344.9 4438.9,7327.2 4401.6,7308.9 4364.6,7289.9 4328,7270.1 4291.7,7249.7 4255.9,7228.5 4220.5,7206.7 4185.5,7184.2 4150.9,7161 4116.8,7137.2 4083.2,7112.7 4050,7087.5 4017.4,7061.8 3985.2,7035.4 3953.5,7008.4 3922.4,6980.8 3891.8,6952.6 3861.8,6923.8 3832.3,6894.5 3803.4,6864.6 3775,6834.1 3747.3,6803.1 3720.1,6771.6 3693.6,6739.5 3667.7,6707 3642.4,6673.9 3617.7,6640.4 3593.7,6606.4 3570.4,6572 3547.7,6537.1 3525.7,6501.8 3504.4,6466.1 3483.7,6429.9 3463.8,6393.4 3444.6,6356.5 3426.1,6319.3 3408.3,6281.7 3391.2,6243.7 3374.9,6205.4 3359.3,6166.9 3344.4,6128 3330.3,6088.9 3317,6049.5 3304.4,6009.8 3292.6,5969.9 3281.5,5929.8 3271.2,5889.5 3261.7,5849 3253,5808.3 3245,5767.5 3237.9,5726.5 3231.5,5685.4 3225.9,5644.1 3221.1,5602.8 3217.1,5561.4 3213.9,5519.9 3211.6,5478.4 3210,5436.8 3209.2,5395.2 3209.2,5353.6

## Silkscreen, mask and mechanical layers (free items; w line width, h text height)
Top Silkscreen Layer:
  drawing of 4 lines, arcs and shapes, not listed
Bottom Silkscreen Layer:
  drawing of 4335 lines, arcs and shapes, not listed
  text "@TWNINKLY09" at 5744.4,6719.4 h120
Mechanical Layer:
  drawing of 252 lines, arcs and shapes, not listed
